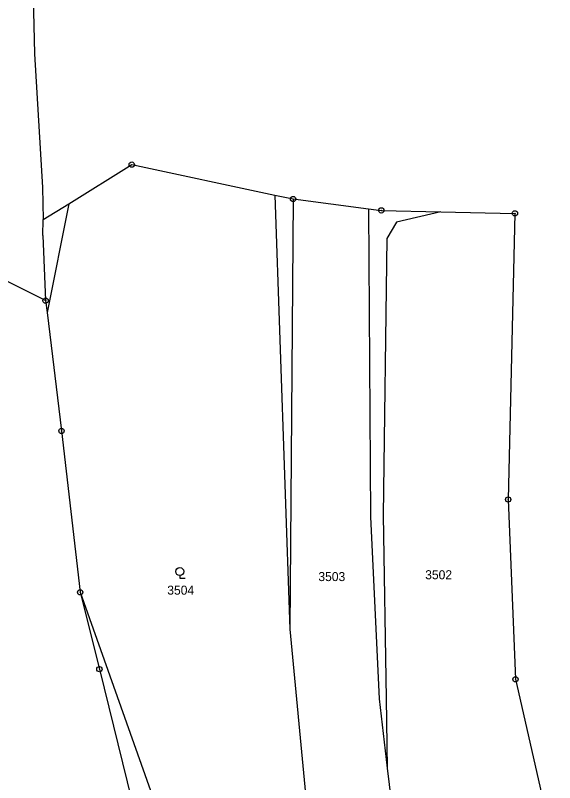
# Model space of a CAD drawing. Extents: x -593183 to -588034, y -1130415 to -1124994.
# Drawn here: x -593070.9 to -592969.5, y -1129057.9 to -1128913.5 of the extents above; entities that cross this region are included whole.
import ezdxf

# ---------------------------------------------------------------- set-up
doc = ezdxf.new("R2010")
doc.units = 0
for name, color, linetype in [('Vrstva 1', 7, 'Continuous'), ('Vrstva 13', 7, 'Continuous'), ('Vrstva 18', 7, 'Continuous'), ('Vrstva 24', 7, 'Continuous'), ('Vrstva 25', 7, 'Continuous'), ('Vrstva 4', 7, 'Continuous')]:
    doc.layers.add(name, color=color, linetype=linetype)

msp = doc.modelspace()

# ---------------------------------------------------------------- linework, layer by layer
at = {"layer": 'Vrstva 1'}
for p, q in [((-593060.84, -1128948.92), (-593048.99, -1128941.56)), ((-593048.99, -1128941.56), (-593022.07, -1128947.31)), ((-593022.07, -1128947.31), (-593018.65, -1128948.04)), ((-593065.66, -1128951.91), (-593060.84, -1128948.92)), ((-593018.65, -1128948.04), (-593019.24, -1129029)), ((-593018.65, -1128948.04), (-593004.45, -1128949.88)), ((-593004.45, -1128949.88), (-593002.05, -1128950.19)), ((-593004.45, -1128949.88), (-593004.08, -1129007.85)), ((-593002.05, -1128950.19), (-592990.85, -1128950.44)), ((-592990.85, -1128950.44), (-592976.92, -1128950.74)), ((-592976.92, -1128950.74), (-592978.2, -1129004.58)), ((-593065.2, -1128967.17), (-593064.93, -1128969.42)), ((-593064.93, -1128969.42), (-593062.2, -1128991.68)), ((-593062.2, -1128991.68), (-593058.7, -1129022.05)), ((-592978.2, -1129004.58), (-592976.82, -1129038.42)), ((-593004.08, -1129007.85), (-593002.44, -1129042.08)), ((-593058.7, -1129022.05), (-593055.08, -1129036.52)), ((-593058.7, -1129022.05), (-593042.63, -1129067.21)), ((-593019.24, -1129029), (-593012.64, -1129098.9)), ((-593055.08, -1129036.52), (-593046.87, -1129069.86)), ((-592976.82, -1129038.42), (-592969.45, -1129070.84)), ((-593002.44, -1129042.08), (-593000.92, -1129055.13)), ((-593000.92, -1129055.13), (-592995.92, -1129098.16))]:
    msp.add_line(p, q, dxfattribs=at)
at = {"layer": 'Vrstva 13'}
for p, q in [((-593067.87, -1128897.04), (-593067.29, -1128920.7)), ((-593067.29, -1128920.7), (-593065.75, -1128945.87)), ((-593065.75, -1128945.87), (-593065.66, -1128951.91)), ((-593065.74, -1128954.91), (-593065.66, -1128951.91)), ((-593065.74, -1128954.91), (-593065.2, -1128967.17)), ((-593065.2, -1128967.17), (-593088.84, -1128955.29))]:
    msp.add_line(p, q, dxfattribs=at)
at = {"layer": 'Vrstva 24'}
for centre, radius in [((-593048.99, -1128941.56), 0.5), ((-593048.99, -1128941.56), 0.0327), ((-593018.65, -1128948.04), 0.5), ((-593018.65, -1128948.04), 0.0327), ((-593002.05, -1128950.19), 0.5), ((-593002.05, -1128950.19), 0.0327), ((-592976.92, -1128950.74), 0.5), ((-592976.92, -1128950.74), 0.0327), ((-593065.2, -1128967.17), 0.5), ((-593065.2, -1128967.17), 0.0327), ((-593062.2, -1128991.68), 0.5), ((-593062.2, -1128991.68), 0.0327), ((-592978.2, -1129004.58), 0.5), ((-592978.2, -1129004.58), 0.0327), ((-593058.7, -1129022.05), 0.5), ((-593058.7, -1129022.05), 0.0327), ((-593055.08, -1129036.52), 0.5), ((-593055.08, -1129036.52), 0.0327), ((-592976.82, -1129038.42), 0.5), ((-592976.82, -1129038.42), 0.0327)]:
    msp.add_circle(centre, radius, dxfattribs=at)
at = {"layer": 'Vrstva 25'}
for p, q in [((-593039.95, -1129018.89), (-593039.95, -1129019.39)), ((-593039.95, -1129019.39), (-593038.93, -1129019.39))]:
    msp.add_line(p, q, dxfattribs=at)
msp.add_circle((-593039.95, -1129018.14), 0.75, dxfattribs=at)
at = {"layer": 'Vrstva 4'}
for p, q in [((-593022.07, -1128947.31), (-593019.24, -1129029)), ((-593060.84, -1128948.92), (-593064.93, -1128969.42)), ((-592990.85, -1128950.44), (-592999.18, -1128952.37)), ((-592999.18, -1128952.37), (-593001.01, -1128955.48)), ((-593001.01, -1128955.48), (-593001.71, -1129007.55)), ((-593001.71, -1129007.55), (-593001.14, -1129042.02)), ((-593001.14, -1129042.02), (-593000.92, -1129055.13))]:
    msp.add_line(p, q, dxfattribs=at)

# ---------------------------------------------------------------- texts
at = {"layer": 'Vrstva 18'}
for s, p in [('3503', (-593013.89, -1129019.94)), ('3502', (-592993.8, -1129019.6)), ('3504', (-593042.31, -1129022.5))]:
    msp.add_text(s, height=1.7, dxfattribs=at).set_placement(p)

doc.saveas('drawing.dxf')
